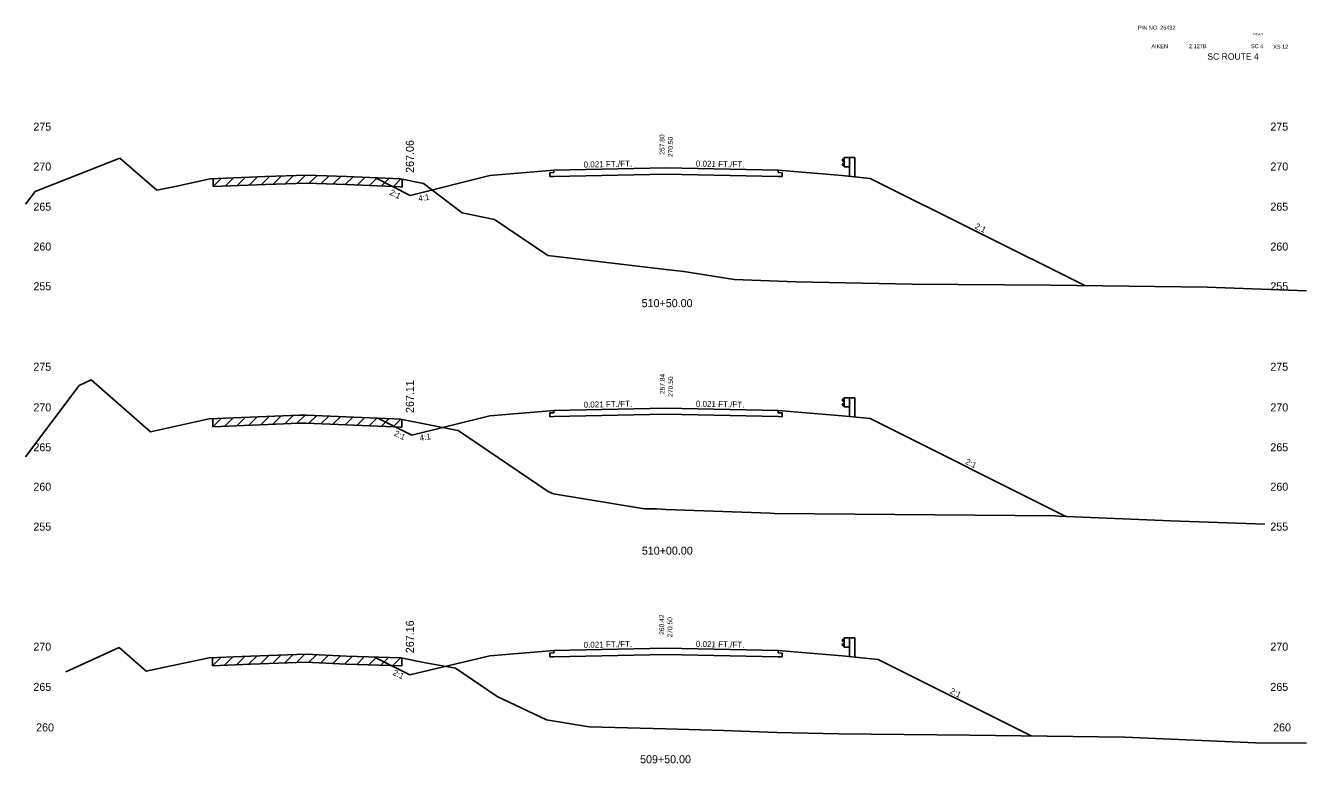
# Model space of a CAD drawing. Extents: x 883 to 1160, y 1002 to 4323.
# Drawn here: x 1000 to 1160, y 2276.1 to 2368.3 of the extents above; entities that cross this region are included whole.
import ezdxf

# ---------------------------------------------------------------- set-up
doc = ezdxf.new("R2010")
doc.units = 0
for name, color, linetype in [('Level 1', 7, 'Continuous'), ('Level 10', 7, 'Continuous'), ('Level 11', 7, 'Continuous'), ('Level 12', 7, 'Continuous'), ('Level 24', 7, 'Continuous'), ('Level 3', 7, 'Continuous'), ('Level 32', 7, 'Continuous'), ('Level 33', 7, 'Continuous'), ('Level 59', 7, 'Continuous'), ('Level 6', 7, 'Continuous'), ('Level 60', 7, 'Continuous'), ('Level 61', 7, 'Continuous'), ('Level 7', 7, 'Continuous')]:
    doc.layers.add(name, color=color, linetype=linetype)

msp = doc.modelspace()

# ---------------------------------------------------------------- linework, layer by layer
at = {"layer": 'Level 11'}
for p, q in [((1066, 2349.91), (1065.5, 2349.9)), ((1065.5, 2349.9), (1065.5, 2349.42)), ((1065.5, 2349.42), (1066, 2349.43)), ((1066, 2350.21), (1066, 2349.91)), ((1094, 2349.91), (1094, 2350.21)), ((1094.5, 2349.9), (1094, 2349.91)), ((1094, 2349.43), (1094.5, 2349.42)), ((1094.5, 2349.42), (1094.5, 2349.9)), ((1066, 2320.21), (1066, 2319.91)), ((1094, 2319.91), (1094, 2320.21)), ((1066, 2319.91), (1065.5, 2319.9)), ((1065.5, 2319.9), (1065.5, 2319.42)), ((1065.5, 2319.42), (1066, 2319.43)), ((1094.5, 2319.9), (1094, 2319.91)), ((1094, 2319.43), (1094.5, 2319.42)), ((1094.5, 2319.42), (1094.5, 2319.9)), ((1066, 2289.91), (1065.5, 2289.9)), ((1065.5, 2289.9), (1065.5, 2289.42)), ((1066, 2290.21), (1066, 2289.91)), ((1094, 2289.91), (1094, 2290.21)), ((1094.5, 2289.9), (1094, 2289.91)), ((1094.5, 2289.42), (1094.5, 2289.9)), ((1065.5, 2289.42), (1066, 2289.43)), ((1094, 2289.43), (1094.5, 2289.42))]:
    msp.add_line(p, q, dxfattribs=at)
at = {"layer": 'Level 12'}
for p, q in [((1080, 2349.72), (1066, 2349.43)), ((1094, 2349.43), (1080, 2349.72)), ((1080, 2319.72), (1066, 2319.43)), ((1094, 2319.43), (1080, 2319.72)), ((1080, 2289.72), (1066, 2289.43)), ((1094, 2289.43), (1080, 2289.72))]:
    msp.add_line(p, q, dxfattribs=at)
at = {"layer": 'Level 24'}
for p, q in [((1102.27, 2351.72), (1102, 2351.52)), ((1102, 2351.52), (1102, 2351.47)), ((1102, 2351.47), (1102.27, 2351.27)), ((1102, 2350.95), (1102.27, 2351.15)), ((1102, 2350.9), (1102, 2350.95)), ((1102.27, 2350.7), (1102, 2350.9)), ((1102.27, 2350.63), (1102.27, 2351.79)), ((1102.27, 2351.79), (1102.94, 2351.79)), ((1102.27, 2350.63), (1102.94, 2350.63)), ((1102.94, 2351.79), (1102.94, 2349.45)), ((1102.94, 2351.79), (1103.6, 2351.79)), ((1103.6, 2351.79), (1103.6, 2349.38)), ((1102.27, 2321.72), (1102, 2321.52)), ((1102.27, 2320.63), (1102.27, 2321.79)), ((1102.27, 2321.79), (1102.94, 2321.79)), ((1102.94, 2321.79), (1102.94, 2319.45)), ((1102.94, 2321.79), (1103.6, 2321.79)), ((1103.6, 2321.79), (1103.6, 2319.38)), ((1102, 2321.52), (1102, 2321.47)), ((1102, 2321.47), (1102.27, 2321.27)), ((1102, 2320.95), (1102.27, 2321.15)), ((1102, 2320.9), (1102, 2320.95)), ((1102.27, 2320.7), (1102, 2320.9)), ((1102.27, 2320.63), (1102.94, 2320.63)), ((1102.27, 2291.72), (1102, 2291.52)), ((1102, 2291.52), (1102, 2291.47)), ((1102, 2291.47), (1102.27, 2291.27)), ((1102.27, 2290.63), (1102.27, 2291.79)), ((1102.27, 2291.79), (1102.94, 2291.79)), ((1102.94, 2291.79), (1102.94, 2289.45)), ((1102.94, 2291.79), (1103.6, 2291.79)), ((1103.6, 2291.79), (1103.6, 2289.38)), ((1102, 2290.95), (1102.27, 2291.15)), ((1102, 2290.9), (1102, 2290.95)), ((1102.27, 2290.7), (1102, 2290.9)), ((1102.27, 2290.63), (1102.94, 2290.63))]:
    msp.add_line(p, q, dxfattribs=at)
at = {"layer": 'Level 59'}
for p, q in [((1066, 2350.21), (1080, 2350.5)), ((1080, 2350.5), (1094, 2350.21)), ((1066, 2320.21), (1080, 2320.5)), ((1080, 2320.5), (1094, 2320.21)), ((1066, 2290.21), (1080, 2290.5)), ((1080, 2290.5), (1094, 2290.21))]:
    msp.add_line(p, q, dxfattribs=at)
at = {"layer": 'Level 6'}
for p, q in [((1058, 2349.54), (1066, 2350.21)), ((1094, 2350.21), (1102, 2349.54)), ((1102, 2349.54), (1105.5, 2349.19)), ((1058, 2319.54), (1066, 2320.21)), ((1094, 2320.21), (1102, 2319.54)), ((1102, 2319.54), (1105.5, 2319.19)), ((1058, 2289.54), (1066, 2290.21)), ((1094, 2290.21), (1102, 2289.54)), ((1102, 2289.54), (1106.5, 2289.09))]:
    msp.add_line(p, q, dxfattribs=at)
at = {"layer": 'Level 60'}
for p, q in [((1001.18, 2347.53), (1011.79, 2351.72)), ((1011.79, 2351.72), (1016.39, 2347.7)), ((1018.89, 2348.23), (1023.07, 2349.14)), ((1023.07, 2349.14), (1029.98, 2349.42)), ((1029.98, 2349.42), (1035.08, 2349.6)), ((1035.08, 2349.6), (1040.09, 2349.43)), ((1040.09, 2349.43), (1046.84, 2349.13)), ((1046.84, 2349.13), (1049.69, 2348.56)), ((1000, 2345.96), (1001.18, 2347.53)), ((1016.39, 2347.7), (1018.89, 2348.23)), ((1049.69, 2348.56), (1054.54, 2344.88)), ((1054.54, 2344.88), (1058.59, 2344.06)), ((1058.59, 2344.06), (1065.23, 2339.56)), ((1065.23, 2339.56), (1080, 2337.81)), ((1080, 2337.81), (1082.21, 2337.54)), ((1082.21, 2337.54), (1088.53, 2336.54)), ((1088.53, 2336.54), (1096.28, 2336.28)), ((1096.28, 2336.28), (1110.74, 2335.97)), ((1110.74, 2335.97), (1128.03, 2335.84)), ((1128.03, 2335.84), (1147.59, 2335.59)), ((1147.59, 2335.59), (1160, 2335.12)), ((1000, 2314.41), (1006.68, 2323.32)), ((1006.68, 2323.32), (1008.19, 2324.02)), ((1008.19, 2324.02), (1015.59, 2317.54)), ((1015.59, 2317.54), (1022.35, 2319.03)), ((1022.35, 2319.03), (1022.95, 2319.15)), ((1022.95, 2319.15), (1034.17, 2319.6)), ((1034.17, 2319.6), (1035.03, 2319.63)), ((1035.03, 2319.63), (1045.99, 2319.14)), ((1045.99, 2319.14), (1046.85, 2319.12)), ((1046.85, 2319.12), (1053.58, 2317.78)), ((1053.58, 2317.78), (1054.02, 2317.7)), ((1054.02, 2317.7), (1065.29, 2310.07)), ((1065.29, 2310.07), (1065.93, 2309.77)), ((1065.93, 2309.77), (1077.32, 2307.93)), ((1077.32, 2307.93), (1078.81, 2307.89)), ((1078.81, 2307.89), (1080, 2307.84)), ((1080, 2307.84), (1093.01, 2307.36)), ((1093.01, 2307.36), (1093.55, 2307.34)), ((1093.55, 2307.34), (1128.62, 2307.02)), ((1128.62, 2307.02), (1129.03, 2307.01)), ((1129.03, 2307.01), (1143.08, 2306.43)), ((1143.08, 2306.43), (1154.81, 2305.98)), ((1005.03, 2287.54), (1011.67, 2290.6)), ((1011.67, 2290.6), (1015.07, 2287.62)), ((1028.09, 2289.5), (1035.01, 2289.74)), ((1035.01, 2289.74), (1040.06, 2289.52)), ((1015.07, 2287.62), (1018.19, 2288.3)), ((1018.19, 2288.3), (1022.92, 2289.29)), ((1022.92, 2289.29), (1028.09, 2289.5)), ((1040.06, 2289.52), (1046.86, 2289.3)), ((1046.86, 2289.3), (1049.97, 2288.68)), ((1049.97, 2288.68), (1053.7, 2288)), ((1053.7, 2288), (1058.92, 2284.46)), ((1058.92, 2284.46), (1065.08, 2281.55)), ((1065.08, 2281.55), (1070.39, 2280.69)), ((1070.39, 2280.69), (1080, 2280.42)), ((1080, 2280.42), (1087.2, 2280.21)), ((1087.2, 2280.21), (1093.83, 2279.97)), ((1093.83, 2279.97), (1101.55, 2279.8)), ((1101.55, 2279.8), (1117.91, 2279.65)), ((1117.91, 2279.65), (1137.3, 2279.38)), ((1137.3, 2279.38), (1153.66, 2278.7)), ((1153.66, 2278.7), (1160, 2278.65))]:
    msp.add_line(p, q, dxfattribs=at)
at = {"layer": 'Level 61'}
for p, q in [((1024.48, 2349.2), (1023.44, 2348.16)), ((1023.44, 2349.16), (1023.44, 2348.16)), ((1025.98, 2349.26), (1024.94, 2348.22)), ((1027.48, 2349.32), (1026.44, 2348.28)), ((1028.98, 2349.38), (1027.94, 2348.34)), ((1030.48, 2349.44), (1029.44, 2348.4)), ((1031.98, 2349.49), (1030.94, 2348.45)), ((1033.48, 2349.54), (1032.44, 2348.51)), ((1034.98, 2349.6), (1033.94, 2348.56)), ((1036.41, 2349.56), (1035.44, 2348.59)), ((1037.91, 2349.5), (1036.94, 2348.54)), ((1039.41, 2349.45), (1038.44, 2348.49)), ((1040.9, 2349.39), (1039.94, 2348.44)), ((1042.4, 2349.33), (1041.44, 2348.37)), ((1043.9, 2349.26), (1042.94, 2348.3)), ((1045.4, 2349.2), (1044.44, 2348.24)), ((1046.89, 2349.12), (1045.94, 2348.17)), ((1047.02, 2348.1), (1047.02, 2349.1)), ((1023.44, 2348.16), (1029.98, 2348.42)), ((1029.98, 2348.42), (1035.08, 2348.6)), ((1035.08, 2348.6), (1040.09, 2348.43)), ((1040.09, 2348.43), (1046.84, 2348.13)), ((1046.84, 2348.13), (1047.02, 2348.1)), ((1024.44, 2319.21), (1023.4, 2318.17)), ((1023.4, 2319.17), (1023.4, 2318.17)), ((1023.4, 2318.17), (1034.17, 2318.6)), ((1025.94, 2319.27), (1024.9, 2318.23)), ((1027.44, 2319.33), (1026.4, 2318.29)), ((1028.94, 2319.39), (1027.9, 2318.35)), ((1030.44, 2319.45), (1029.4, 2318.41)), ((1031.94, 2319.51), (1030.9, 2318.47)), ((1033.44, 2319.57), (1032.4, 2318.53)), ((1034.94, 2319.62), (1033.9, 2318.59)), ((1034.17, 2318.6), (1035.03, 2318.63)), ((1035.03, 2318.63), (1045.99, 2318.14)), ((1036.36, 2319.57), (1035.4, 2318.61)), ((1037.86, 2319.5), (1036.9, 2318.54)), ((1039.36, 2319.44), (1038.4, 2318.48)), ((1040.86, 2319.37), (1039.9, 2318.41)), ((1042.36, 2319.3), (1041.4, 2318.35)), ((1043.86, 2319.24), (1042.9, 2318.28)), ((1045.36, 2319.17), (1044.4, 2318.21)), ((1046.86, 2319.11), (1045.9, 2318.15)), ((1047, 2318.09), (1047, 2319.09)), ((1045.99, 2318.14), (1046.85, 2318.12)), ((1046.85, 2318.12), (1047, 2318.09)), ((1031.89, 2289.63), (1030.86, 2288.59)), ((1033.39, 2289.68), (1032.36, 2288.65)), ((1034.89, 2289.74), (1033.86, 2288.7)), ((1036.32, 2289.68), (1035.36, 2288.73)), ((1037.82, 2289.62), (1036.86, 2288.66)), ((1024.4, 2289.35), (1023.36, 2288.31)), ((1023.36, 2289.31), (1023.36, 2288.31)), ((1023.36, 2288.31), (1028.09, 2288.5)), ((1025.9, 2289.41), (1024.86, 2288.37)), ((1027.4, 2289.47), (1026.36, 2288.43)), ((1028.9, 2289.52), (1027.86, 2288.49)), ((1028.09, 2288.5), (1035.01, 2288.74)), ((1030.39, 2289.58), (1029.36, 2288.54)), ((1035.01, 2288.74), (1040.06, 2288.52)), ((1039.32, 2289.55), (1038.36, 2288.59)), ((1040.82, 2289.5), (1039.86, 2288.53)), ((1040.06, 2288.52), (1046.86, 2288.3)), ((1042.33, 2289.45), (1041.36, 2288.48)), ((1043.83, 2289.4), (1042.86, 2288.43)), ((1045.33, 2289.35), (1044.36, 2288.38)), ((1046.83, 2289.3), (1045.86, 2288.33)), ((1046.86, 2288.3), (1046.98, 2288.28)), ((1046.98, 2288.28), (1046.98, 2289.28))]:
    msp.add_line(p, q, dxfattribs=at)
at = {"layer": 'Level 7'}
for p, q in [((1043.61, 2349.28), (1048.05, 2347.06)), ((1058, 2349.54), (1048.05, 2347.06)), ((1105.5, 2349.19), (1132.31, 2335.79)), ((1044, 2319.23), (1048.25, 2317.11)), ((1058, 2319.54), (1048.25, 2317.11)), ((1105.5, 2319.19), (1129.94, 2306.97)), ((1043.49, 2289.41), (1048, 2287.16)), ((1048, 2287.16), (1058, 2289.54)), ((1106.5, 2289.09), (1125.6, 2279.54))]:
    msp.add_line(p, q, dxfattribs=at)

# ---------------------------------------------------------------- texts
at = {"layer": 'Level 1'}
for s, height, p in [('PIN NO. 26432', 0.5, (1138.97, 2367.76)), ('AIKEN', 0.5, (1140.64, 2365.45)), (' 2.127B', 0.5, (1145.15, 2365.45)), ('SC ROUTE 4', 0.8, (1147.63, 2364.01)), ('SC 4', 0.5, (1153.09, 2365.45)), ('XS 12', 0.5, (1155.85, 2365.39)), ('510+50.00', 1, (1076.96, 2333.1)), ('510+00.00', 1, (1076.98, 2302.18)), ('509+50.00', 1, (1076.76, 2276.13))]:
    msp.add_text(s, height=height, dxfattribs=at).set_placement(p)
at = {"layer": 'Level 10'}
for s, p in [('257.80', (1079.81, 2352.15)), ('257.84', (1079.84, 2322.24)), ('260.42', (1079.77, 2292.18))]:
    msp.add_text(s, height=0.6, rotation=90, dxfattribs=at).set_placement(p)
at = {"layer": 'Level 3'}
for s, height, p in [('ROAD', 0.3, (1153.38, 2367.04)), (' 275', 1, (1000.6, 2355.15)), (' 275', 1, (1155.13, 2355.15)), (' 270', 1, (1000.6, 2350.17)), (' 270', 1, (1155.13, 2350.17)), (' 265', 1, (1000.6, 2345.15)), (' 265', 1, (1155.13, 2345.15)), (' 260', 1, (1000.6, 2340.17)), (' 260', 1, (1155.13, 2340.17)), (' 255', 1, (1000.6, 2335.21)), (' 255', 1, (1155.13, 2335.21)), (' 275', 1, (1000.6, 2325.16)), (' 275', 1, (1155.13, 2325.16)), (' 270', 1, (1000.6, 2320.08)), (' 270', 1, (1155.13, 2320.08)), (' 265', 1, (1000.6, 2315.1)), (' 265', 1, (1155.13, 2315.1)), (' 260', 1, (1000.6, 2310.17)), (' 260', 1, (1155.13, 2310.17)), (' 255', 1, (1000.6, 2305.19)), (' 255', 1, (1155.13, 2305.19)), (' 270', 1, (1000.6, 2290.19)), (' 270', 1, (1155.13, 2290.19)), (' 265', 1, (1000.6, 2285.17)), (' 265', 1, (1155.13, 2285.17)), (' 260', 1, (1000.94, 2280.11)), (' 260', 1, (1155.47, 2280.11))]:
    msp.add_text(s, height=height, dxfattribs=at).set_placement(p)
at = {"layer": 'Level 32'}
for s, rotation, p in [('0.021 FT./FT.', 1.1916, (1069.71, 2350.54)), ('0.021 FT./FT.', 358.8084, (1083.72, 2350.67)), ('2:1', 333.435, (1045.39, 2347.2)), ('4:1', 9.4623, (1049.12, 2346.29)), ('2:1', 333.435, (1118.51, 2342.97)), ('0.021 FT./FT.', 1.1916, (1069.71, 2320.54)), ('0.021 FT./FT.', 358.8084, (1083.72, 2320.67)), ('2:1', 333.435, (1045.96, 2317.09)), ('4:1', 9.4623, (1049.28, 2316.38)), ('2:1', 333.435, (1117.32, 2313.56)), ('0.021 FT./FT.', 1.1916, (1069.71, 2290.54)), ('0.021 FT./FT.', 358.8084, (1083.72, 2290.67)), ('2:1', 333.435, (1045.8, 2287.21)), ('2:1', 333.435, (1115.39, 2284.91))]:
    msp.add_text(s, height=0.75, rotation=rotation, dxfattribs=at).set_placement(p)
at = {"layer": 'Level 33'}
for s, p in [('267.06', (1048.5, 2349.88)), ('267.11', (1048.5, 2319.88)), ('267.16', (1048.5, 2289.88))]:
    msp.add_text(s, height=1, rotation=90, dxfattribs=at).set_placement(p)
at = {"layer": 'Level 59'}
for p in [(1080.85, 2351.62), (1080.88, 2321.68), (1080.79, 2291.62)]:
    msp.add_text(' 270.50', height=0.6, rotation=90, dxfattribs=at).set_placement(p)

doc.saveas('drawing.dxf')
